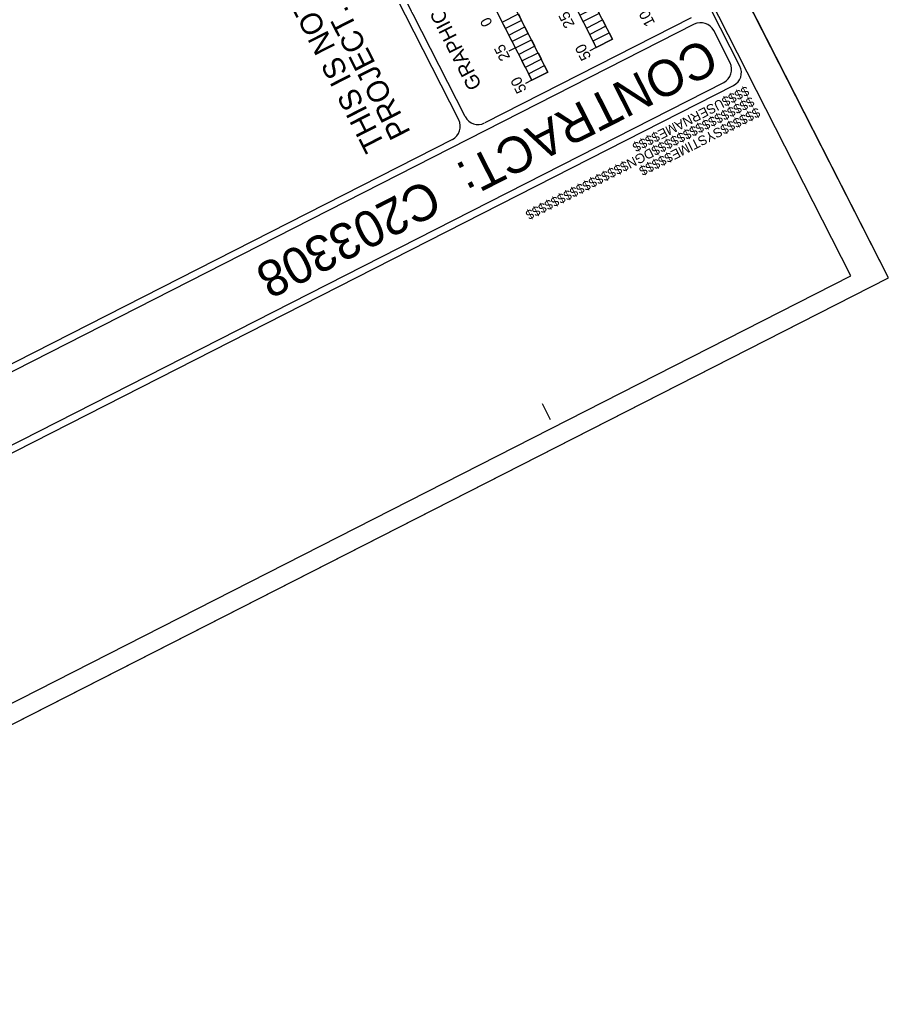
# Model space of a CAD drawing. Extents: x 558484 to 564063, y 513718 to 518374.
# Drawn here: x 559790 to 560390, y 514425 to 515102 of the extents above; entities that cross this region are included whole.
import ezdxf

# ---------------------------------------------------------------- set-up
doc = ezdxf.new("R2010")
doc.units = 0
for name, color, linetype in [('Default', 7, 'Continuous'), ('Sheet Cutting Line CELL', 7, 'Continuous'), ('Sheet Data Field CELL', 7, 'Continuous'), ('Sheet Plot Border Inside CELL', 7, 'Continuous'), ('Sheet Plot Border Outside CELL', 7, 'Continuous'), ('Sheet Title CELL', 7, 'Continuous')]:
    doc.layers.add(name, color=color, linetype=linetype)

msp = doc.modelspace()

# ---------------------------------------------------------------- linework, layer by layer
at = {"layer": 'Sheet Cutting Line CELL'}
for p, q in [((560390.41, 514923.75), (559626.36, 516424.45)), ((559410.15, 514424.68), (560390.41, 514923.75))]:
    msp.add_line(p, q, dxfattribs=at)
at = {"layer": 'Sheet Data Field CELL'}
for p, q in [((560132.67, 515082.62), (560128.22, 515080.35)), ((560132.67, 515082.62), (560128.22, 515080.35)), ((560144, 515060.34), (560139.56, 515058.07)), ((560144, 515060.34), (560139.56, 515058.07)), ((560292.35, 515061.24), (560292.35, 515061.24)), ((560292.35, 515061.24), (560292.35, 515061.24))]:
    msp.add_line(p, q, dxfattribs=at)
at = {"layer": 'Sheet Plot Border Inside CELL'}
msp.add_lwpolyline([(560364.51, 514925.16), (559608.41, 516410.26), (558668.16, 515931.55), (559424.26, 514446.45)], close=True, dxfattribs=at)
at = {"layer": 'Sheet Plot Border Outside CELL'}
msp.add_lwpolyline([(558646.11, 515925.37), (559410.15, 514424.68), (560390.41, 514923.75), (559626.36, 516424.45)], close=True, dxfattribs=at)
at = {"layer": 'Sheet Title CELL'}
for p, q in [((560093.55, 515032.95), (559449.28, 516298.38)), ((560199.72, 515088.69), (560131.66, 515222.36)), ((560120.52, 515216.69), (560188.59, 515083.02)), ((560120.52, 515216.69), (560188.59, 515083.02)), ((560075.96, 515194), (560144.02, 515060.33)), ((560155.16, 515066), (560087.12, 515199.68)), ((560098.02, 515035.23), (560027.68, 515173.35)), ((560256.31, 515098.98), (559347.33, 514636.2)), ((560254.04, 515103.46), (560111.45, 515030.85)), ((560128.14, 515091.52), (560139.28, 515097.19)), ((560188.59, 515083.02), (560199.72, 515088.69)), ((560132.69, 515082.62), (560128.22, 515080.34)), ((560188.59, 515083.02), (560184.12, 515080.75)), ((560188.59, 515083.02), (560184.12, 515080.75)), ((560184.12, 515080.75), (560184.12, 515080.75)), ((560188.59, 515083.02), (560188.59, 515083.02)), ((560188.59, 515083.02), (560188.59, 515083.02)), ((560144.02, 515060.33), (560155.16, 515066)), ((560144.02, 515060.33), (560139.58, 515058.07)), ((560139.58, 515058.07), (560139.58, 515058.07)), ((560144.02, 515060.33), (560144.02, 515060.33)), ((560292.36, 515061.23), (560292.36, 515061.23)), ((560292.36, 515061.23), (560292.36, 515061.23)), ((560292.36, 515061.23), (560292.36, 515061.23)), ((560292.36, 515061.23), (560292.36, 515061.23)), ((560089.18, 515019.5), (559345.07, 514640.66)), ((560157.01, 514825.68), (560151.33, 514836.82)), ((560157.01, 514825.68), (560151.33, 514836.82))]:
    msp.add_line(p, q, dxfattribs=at)
for points in [[(560287.83, 515070.15), (559616.34, 516389.05)], [(560281.1, 515072.32), (560269.76, 515094.61)], [(559367.75, 514596.11), (560276.72, 515058.88)], [(559365.56, 514589.37), (560283.45, 515056.69)], [(559365.56, 514589.37), (560283.45, 515056.69)]]:
    msp.add_lwpolyline(points, dxfattribs=at)
for points in [[(560125.87, 515095.98), (560123.6, 515100.43), (560134.75, 515106.11), (560137.01, 515101.65)], [(560179.5, 515100.84), (560177.24, 515105.31), (560188.38, 515110.97), (560190.66, 515106.52)], [(560184.04, 515091.93), (560181.77, 515096.38), (560192.92, 515102.07), (560195.18, 515097.6)], [(560130.42, 515087.07), (560128.14, 515091.52), (560139.28, 515097.19), (560141.55, 515092.74)], [(560188.59, 515083.02), (560186.31, 515087.47), (560197.45, 515093.14), (560199.72, 515088.69)], [(560134.96, 515078.16), (560132.69, 515082.62), (560143.82, 515088.28), (560146.09, 515083.83)], [(560139.48, 515069.24), (560137.23, 515073.7), (560148.37, 515079.38), (560150.63, 515074.93)], [(560144.02, 515060.33), (560141.75, 515064.79), (560152.89, 515070.46), (560155.16, 515066)]]:
    msp.add_lwpolyline(points, close=True, dxfattribs=at)
for centre, start, end in [((560260.8, 515090.06), 26.98193, 116.98193), ((560272.14, 515067.78), 296.98193, 26.98193), ((560278.87, 515065.59), 296.98193, 26.98193), ((560084.6, 515028.4), 296.98193, 26.98193), ((560106.88, 515039.74), 206.98193, 296.98193)]:
    msp.add_arc(centre, 10, start, end, dxfattribs=at)

# ---------------------------------------------------------------- texts
at = {"layer": 'Default'}
for s, p in [('THIS IS NOT A CONTROL OF ACCESS ', (560043.03, 515015.42)), ('PROJECT.', (560060.56, 515024.34))]:
    msp.add_text(s, height=15, rotation=116.98193, dxfattribs=at).set_placement(p)
at = {"layer": 'Sheet Data Field CELL'}
for s, p in [('25', (560173.84, 515098.71)), ('10', (560229.39, 515099.81)), ('25', (560129.3, 515076.03)), ('50', (560185.25, 515076.33)), ('50', (560140.69, 515053.65))]:
    msp.add_text(s, height=7.5, rotation=116.98193, dxfattribs=at).set_placement(p)
at = {"layer": 'Sheet Title CELL'}
for s, height, rotation, p in [('GRAPHIC SCALES', 9.9996, 116.98193, (560109.74, 515056.69)), ('0', 7.5, 116.98193, (560117.11, 515099.65)), ('CONTRACT:', 25, 206.98193, (560263.73, 515089.99)), ('$$$$USERNAME$$$$', 6.5625, 206.98193, (560292.1, 515056.6)), ('$$$$$$$$$$$$$$$$DGN$$$$$$$$$$$$$$$$', 6.5625, 206.98193, (560295.66, 515049.21)), ('$$$$$$SYSTIME$$$$$', 6.5625, 206.98193, (560299.74, 515041.75)), ('C203308   ', 25, 206.98193, (560072.38, 514992.56))]:
    msp.add_text(s, height=height, rotation=rotation, dxfattribs=at).set_placement(p)

doc.saveas('drawing.dxf')
